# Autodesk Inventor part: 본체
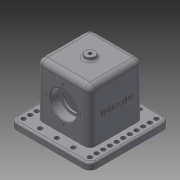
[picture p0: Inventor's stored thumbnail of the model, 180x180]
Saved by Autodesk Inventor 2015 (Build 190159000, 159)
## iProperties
Created: 2018-11
Part Number: 본체
Material: 일반
Document SubType Name: Modeling
Designer: now
Density: 1 g/cm^3
Appearance: 기본값
Mass: 376.063 g
Surface Area: 780.986 cm^2
Volume: 376.063 cm^3
Author: now
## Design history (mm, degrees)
sketch "스케치1"
  geometry: L1 (-60, -60)-(60, -60); L2 (60, -60)-(60, 60); L3 (60, 60)-(-60, 60); L4 (-60, 60)-(-60, -60); L5 (-60, -60)-(60, 60); L6 (60, -60)-(-60, 60); 1 further point
  constraints: 12 end point, 2 midpoint, 2 parallel, 1 horizontal, 1 perpendicular
  dimensions: "d0" = 120 distance of L3.end L1.start; "d1" = 120 distance of L2.end L3.end
extrude "돌출1" new body sketch "스케치1" distance "d2" = 10; taper "d3" = 0 deg
sketch "스케치2"
  geometry: L1 (-40, -40)-(40, -40); L2 (40, -40)-(40, 40); L3 (40, 40)-(-40, 40); L4 (-40, 40)-(-40, -40); L5 (-40, -40)-(40, 40); L6 (40, -40)-(-40, 40); 1 further point
  constraints: 12 end point, 2 midpoint, 2 parallel, 1 horizontal, 1 perpendicular
  dimensions: "d4" = 80 distance of L3.end L1.start; "d5" = 80 distance of L2.end L3.end
extrude "돌출2" join sketch "스케치2" distance "d6" = 80; taper "d7" = 0 deg
fillet "모깎기1" dims "d13" = 10
sketch "스케치6"
  geometry: A1 r 10 centre (-50, -50) between (-60, -50) and (-50, -60) reference; 1 further point
hole "구멍1" sketch "스케치6" at (-50, -50) diameter "d14" = 6.6; stored, may be unused: countersink angle "d18" = 90 deg, drill point angle "d20" = 118 deg; dims "d15" = 6, "d16" = 4, "d17" = 2, "d19" = 8
fillet "모깎기2" dims "d53" = 8
fillet "모깎기3" dims "d60" = 8
fillet "모깎기4" dims "d61" = 8
fillet "모깎기5" dims "d62" = 3
sketch "스케치18"
  geometry: L1 (30, -23)-(-30, -23); L2 (-30, -23)-(-30, 23); L3 (-30, 23)-(30, 23); L4 (30, 23)-(30, -23); L5 (30, -23)-(-30, 23); L6 (-30, -23)-(30, 23); 1 further point
  constraints: 12 end point, 2 midpoint, 2 parallel, 1 horizontal, 1 perpendicular
  dimensions: "d75" = 60 distance of L1.start L1.end; "d76" = 46 distance of L1.end L2.end
extrude "돌출9" cut sketch "스케치18" distance "d77" = 80; taper "d78" = 0 deg
sketch "스케치26"
  geometry: C1 r 16.5 at (32, 38); 1 further point
  constraints: 1 centre point, 1 vertical alignment
  dimensions: "d104" = 48 distance of point (32, -10) C1.centre; "d105" = 33 diameter of C1
extrude "돌출14" cut sketch "스케치26" stored distance "d106" = 3; taper "d107" = 0 deg
sketch "스케치28"
  geometry: C1 r 16.5 at (32, 38) reference; C2 r 20 at (32, 38); 1 further point
  constraints: 1 centre point, 1 coincident
  dimensions: "d108" = 40 diameter of C2
extrude "돌출15" cut sketch "스케치28" distance "d109" = 14; taper "d110" = 0 deg
chamfer "모따기3" distance "d111" = 1; stored, may be unused: second distance "d112" = 2, angle "d113" = 45 deg
sketch "스케치29"
  geometry: C1 r 7.5 at (0, 0); 1 further point
  constraints: 1 centre point, 1 coincident
  dimensions: "d114" = 15 diameter of C1
extrude "돌출16" join sketch "스케치29" distance "d115" = 5; taper "d116" = 0 deg
sketch "스케치30"
  geometry: C1 r 7.5 at (0, 0) reference
hole "구멍5" sketch "스케치30" at (0, 0) diameter "d117" = 4.917; stored, may be unused: countersink angle "d121" = 90 deg, drill point angle "d123" = 118 deg; dims "d118" = 12, "d119" = 4, "d120" = 2, "d122" = 17.1
fillet "모깎기7" dims "d124" = 3
fillet "모깎기8" dims "d125" = 0.6
fillet "모깎기9" dims "d126" = 0.6
sketch "스케치31"
  geometry: C1 r 21 at (32, -38) reference; 2 further points
  constraints: 1 vertical alignment
  dimensions: "d127" = 26 distance of point (32, -64) C1.centre
hole "구멍6" sketch "스케치31" at (32, -64) diameter "d128" = 3.242; stored, may be unused: countersink angle "d132" = 90 deg, drill point angle "d134" = 118 deg; dims "d129" = 8, "d130" = 4, "d131" = 2, "d133" = 10
sketch "스케치32"
  geometry: L1 (10, -18)-(10, 82) reference; 3 further points
  constraints: 1 horizontal alignment, 1 midpoint, 1 other
  dimensions: "d138" = 48 distance from line of L1 point (-38, 32)
fillet "모깎기10" dims "d139" = 3
fillet "모깎기11" dims "d140" = 3
fillet "모깎기12" dims "d141" = 3
feature "엠보싱1" dims "d142" = 0.5, "d143" = 0
node "솔리드1"
pattern_linear "직사각형 패턴4" dims "d56" = 25
pattern_linear "직사각형 패턴5" dims "d59" = 10
mirror "대칭3"
mirror "대칭4"
mirror "대칭5"
pattern_circular "원형 패턴1" dims angle "d136" = 360 deg
mirror "대칭6"
